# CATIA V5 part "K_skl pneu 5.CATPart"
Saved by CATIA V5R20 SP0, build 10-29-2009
Part number: skl pneu 5
Publications: "longueur axe pivot", "Plan.+100", "pneu 5", "Droite.1"
Bounding box of the stored display mesh (mm): x 100 to 250, y 0 to 0, z 0 to 0
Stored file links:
  G:\Khaled_CFAO_2011\SIL\SIL_GR2\mdardier\Khaled\CAD_ThinkMOTION\K_skl pneu 5.CATPart
  G:\Khaled_CFAO_2011\SIL\SIL_GR2\mdardier\Khaled\CAD_ThinkMOTION\K_skl_ass_tandem.CATProduct
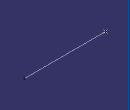
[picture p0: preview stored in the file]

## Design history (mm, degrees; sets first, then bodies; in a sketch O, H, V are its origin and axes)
External parameters (linked from other documents)
  `External.longueur axe pivot` = 150 mm
Set1
  Plane1 "Plan.+100": linked copy from another document
  Point1 "pneu 5": linked copy from another document
Set2
  Line1: type Normal, RefPoint Point1, RefSkin Plane1, Start 0, End 150 {= `External.longueur axe pivot`}
Body1 (main body)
